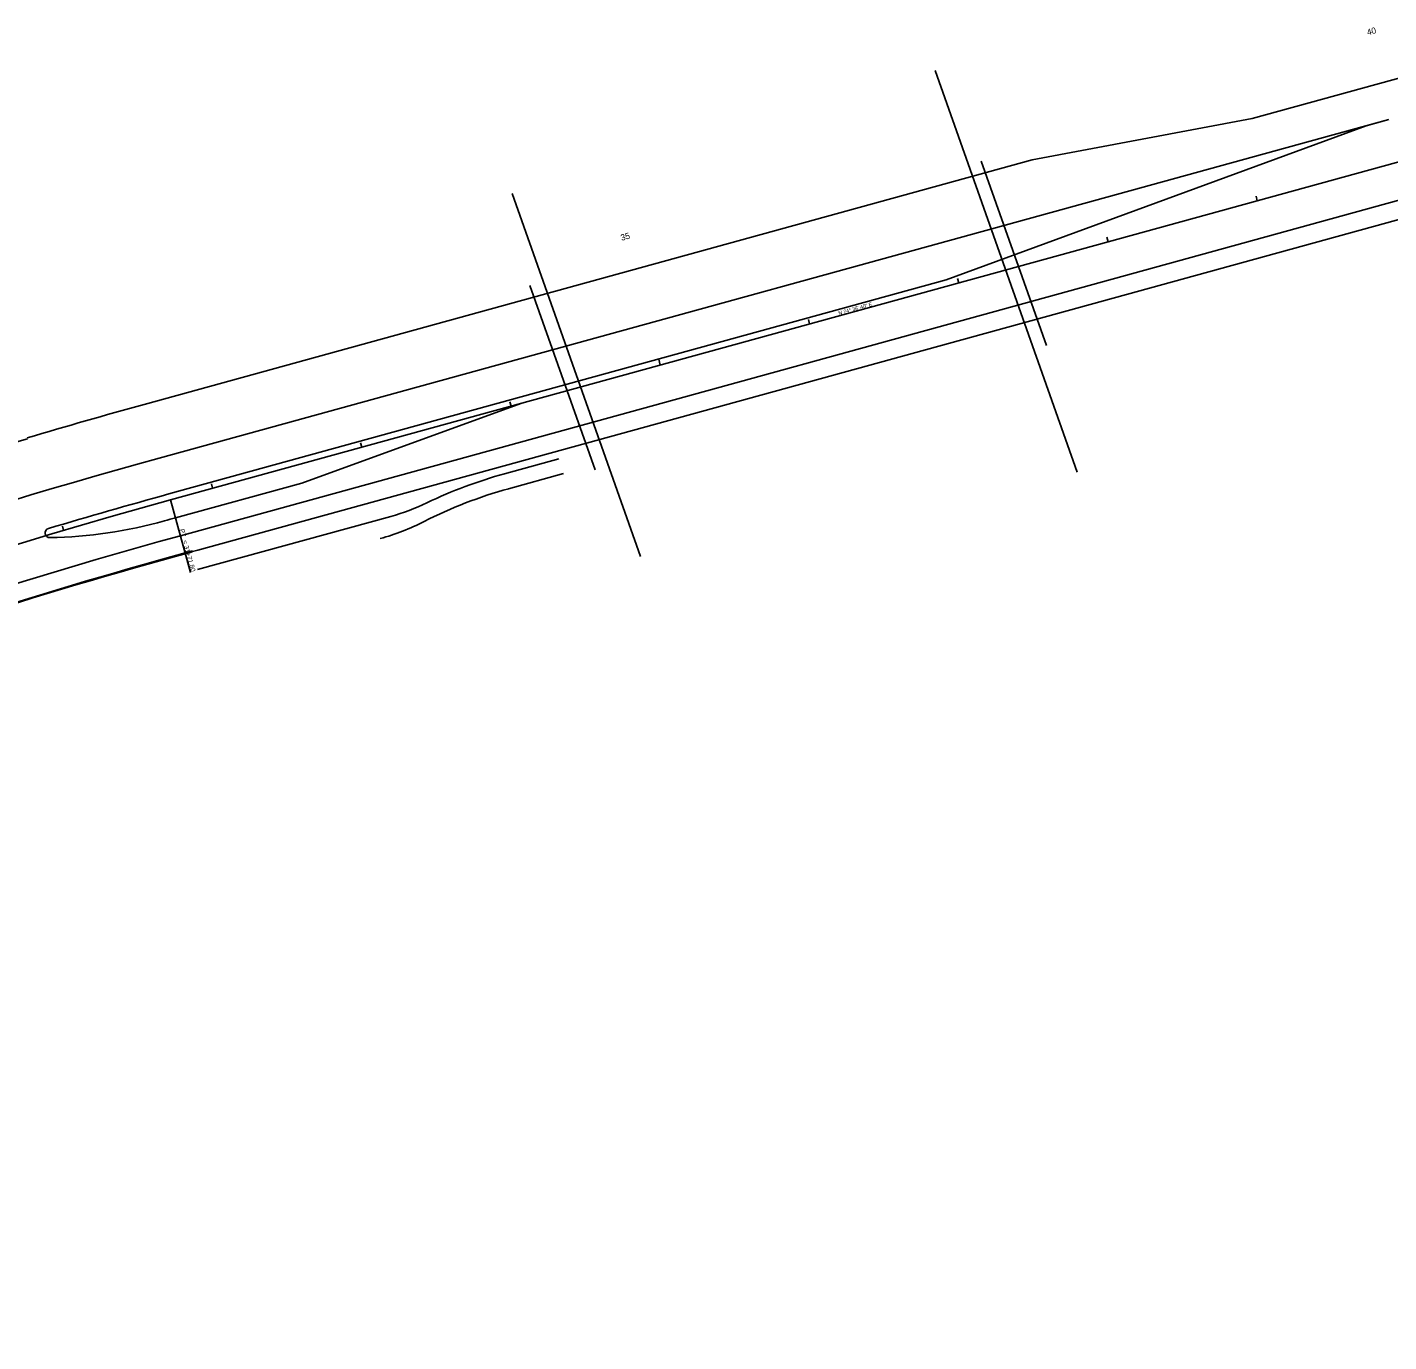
# Model space of a CAD drawing. Extents: x 2004390 to 2007638, y 1136392 to 1138193.
# Drawn here: x 2005442 to 2006322, y 1136432 to 1137281 of the extents above; entities that cross this region are included whole.
import ezdxf

# ---------------------------------------------------------------- set-up
doc = ezdxf.new("R2010")
doc.units = 0
for name, color, linetype in [('RD_HC_Cl', 7, 'Continuous'), ('RD_HC_Data', 7, 'Continuous'), ('RD_HC_Data_Tic', 7, 'Continuous'), ('RD_HC_TX_Sta20', 7, 'Continuous'), ('RD_PD_Bridge', 7, 'Continuous'), ('RD_PD_ConcMed', 7, 'Continuous'), ('RD_PD_Final_TrvlWay', 7, 'Continuous'), ('RD_PD_SideStreet', 7, 'Continuous'), ('RD_PD_SW', 7, 'Continuous'), ('RD_PD_WallCut', 7, 'Continuous')]:
    doc.layers.add(name, color=color, linetype=linetype)

msp = doc.modelspace()

# ---------------------------------------------------------------- linework, layer by layer
at = {"layer": 'RD_HC_Cl'}
msp.add_line((2005534.87, 1136975.91), (2006420.45, 1137219.65), dxfattribs=at)
msp.add_arc((2006499.76, 1133470.27), 3636, 105.38893, 125.45202, dxfattribs=at)
at = {"layer": 'RD_HC_Data'}
msp.add_line((2005534.87, 1136975.91), (2005547.79, 1136928.99), dxfattribs=at)
at = {"layer": 'RD_HC_Data_Tic'}
for p, q in [((2006236.97, 1137169.15), (2006236.17, 1137172.05)), ((2006140.55, 1137142.62), (2006139.76, 1137145.51)), ((2006044.14, 1137116.08), (2006043.34, 1137118.97)), ((2005947.72, 1137089.54), (2005946.93, 1137092.43)), ((2005851.31, 1137063.01), (2005850.25, 1137066.86)), ((2005754.89, 1137036.47), (2005754.1, 1137039.36)), ((2005658.48, 1137009.93), (2005657.68, 1137012.82)), ((2005562.06, 1136983.39), (2005561.27, 1136986.29)), ((2005465.84, 1136956.18), (2005464.99, 1136959.05))]:
    msp.add_line(p, q, dxfattribs=at)
at = {"layer": 'RD_PD_Bridge'}
for p, q in [((2006100.8, 1137075.67), (2006058.67, 1137194.76)), ((2005809.15, 1136995.39), (2005767.02, 1137114.48))]:
    msp.add_line(p, q, dxfattribs=at)
at = {"layer": 'RD_PD_ConcMed'}
for p, q in [((2006035.94, 1137117.97), (2006307.24, 1137217.54)), ((2006307.24, 1137217.54), (2006321.91, 1137221.57)), ((2005533.81, 1136979.77), (2006035.94, 1137117.97)), ((2005619.66, 1136986.8), (2005761.1, 1137038.18)), ((2005538.06, 1136964.34), (2005619.66, 1136986.8))]:
    msp.add_line(p, q, dxfattribs=at)
for centre, radius, start, end in [((2006499.76, 1133470.27), 3640, 105.38893, 106.66257), ((2005450.88, 1137251.49), 300, 271.16177, 285.50353), ((2006499.76, 1133470.27), 3624, 105.38893, 105.50353), ((2005456.9, 1136954.56), 3, 106.66257, 271.16177)]:
    msp.add_arc(centre, radius, start, end, dxfattribs=at)
at = {"layer": 'RD_PD_Final_TrvlWay'}
for p, q in [((2006233.64, 1137222.17), (2006368.1, 1137259.18)), ((2005527.44, 1137002.91), (2006321.91, 1137221.57)), ((2006091.62, 1137195.53), (2006233.64, 1137222.17)), ((2005517.89, 1137037.62), (2006091.62, 1137195.53)), ((2005541.24, 1136952.77), (2006397.86, 1137188.54)), ((2005552.53, 1136943.43), (2006401.04, 1137176.97)), ((2005552.53, 1136943.43), (2005549.18, 1136942.51))]:
    msp.add_line(p, q, dxfattribs=at)
for centre, radius, start, end in [((2006499.76, 1133470.27), 3700, 105.38893, 106.60652), ((2006499.76, 1133470.27), 3664, 105.38893, 119.73334), ((2006499.76, 1133470.27), 3612, 105.38893, 119.73334), ((2006499.76, 1133470.27), 3600, 105.3281, 110.25357), ((2005628.79, 1136653.26), 300, 105.38893, 105.59966)]:
    msp.add_arc(centre, radius, start, end, dxfattribs=at)
at = {"layer": 'RD_PD_SideStreet'}
msp.add_line((2005549.04, 1136942.99), (2005544.29, 1136941.68), dxfattribs=at)
for radius, start, end in [(3699.5, 106.60652, 111.70558), (3600.5, 105.38893, 110.25357)]:
    msp.add_arc((2006499.76, 1133470.27), radius, start, end, dxfattribs=at)
at = {"layer": 'RD_PD_SW'}
for p, q in [((2005750.67, 1136992.78), (2005785.75, 1137002.44)), ((2005753.33, 1136983.14), (2005788.86, 1136992.92)), ((2005552.36, 1136930.94), (2005677.16, 1136965.29))]:
    msp.add_line(p, q, dxfattribs=at)
for centre, radius, start, end in [((2005830.29, 1136703.54), 300, 105.38893, 115.62275), ((2005830.29, 1136703.54), 290, 105.38893, 116.99742), ((2005640.01, 1137100.27), 140, 285.38893, 295.62275), ((2005630.55, 1137095.59), 150, 285.38893, 296.99742)]:
    msp.add_arc(centre, radius, start, end, dxfattribs=at)
at = {"layer": 'RD_PD_WallCut'}
for p, q in [((2006120.62, 1136993.77), (2006028.85, 1137253.18)), ((2005838.59, 1136939.45), (2005755.66, 1137173.89))]:
    msp.add_line(p, q, dxfattribs=at)

# ---------------------------------------------------------------- texts
at = {"layer": 'RD_HC_Data'}
for s, height, rotation, p in [('N 74%%d 36\' 40" E', 2.4, 15.38893, (2005966.74, 1137095.29)), ('PT  = 31+71.80', 3, 285.38893, (2005540.66, 1136956.76))]:
    msp.add_text(s, height=height, rotation=rotation, dxfattribs=at).set_placement(p)
at = {"layer": 'RD_HC_TX_Sta20'}
for s, p in [('40', (2006308.38, 1137275.93)), ('35', (2005826.32, 1137143.25))]:
    msp.add_text(s, height=4, rotation=15.38893, dxfattribs=at).set_placement(p)

doc.saveas('drawing.dxf')
